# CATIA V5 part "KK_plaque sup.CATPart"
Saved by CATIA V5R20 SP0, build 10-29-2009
Part number: plaque fixe de table elevatrice
Bounding box of the stored display mesh (mm): x -103 to 1197, y -355 to 45, z -50 to 50
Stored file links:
  G:\Khaled_CFAO_2011\ST2M\ST2M_GR2\tcorbin\Khaled\CAD_ThinkMOTION\KK_plaque sup.CATPart
  F:\Thinkmotionperso\assemblage robot\ass_skl_robot.CATProduct
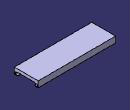
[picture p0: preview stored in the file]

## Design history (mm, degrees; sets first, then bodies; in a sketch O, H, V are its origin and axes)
External parameters (linked from other documents)
  `External.largeur table` = 400 mm
Set1
  Extract1: ExtractElem edge [face of Pad2 from Sketch2.L6 | face of Pad2 from Sketch2.L5]
  Extract2: ExtractElem edge [face of Pad2 from Sketch2.L13 | face of Pad2 from Sketch2.L12]
  Extract3: ExtractElem face of DatumSurface1
  DatumSurface1
  Extract4: ExtractElem face of DatumSurface2
  DatumSurface2
  Fill1: Boundary edge of DatumSurface1
  Healing1: BodyToHeal (Fill1; Extract3), TangencyAngle 0.5, SharpnessAngle 0.5
  Fill2: Boundary edge of DatumSurface2
  Healing2: BodyToHeal (Fill2; Extract4), TangencyAngle 0.5, SharpnessAngle 0.5
Body1 (main body)
  Sketch1 on xy-plane, origin (0, 0, 0), H (1, 0, 0), V (0, 1, 0)
    line L1 (-103, 45) -> (1197, 45)
    line L2 (1197, 45) -> (1197, -355)
    line L3 (1197, -355) -> (-103, -355)
    line L4 (-103, -355) -> (-103, 45)
    length L1 = 1300
    length L4 = 400 {= `External.largeur table`}
    horizontal: L1 H, L3 H
    vertical: L2 V, L4 V
  Pad1: profile Sketch1, direction (0, 0, 1), length 50
  Sketch2 on face of Pad1 from Sketch1.L2, origin (1197, 0, 0), H (0, 1, 0), V (0, 0, 1)
    point P1 (-15, 0)
    line L1 (-15, 0) -> (45, 0)
    line L2 (45, 0) -> (45, -50)
    line L3 (45, -50) -> (-15, -50)
    line L4 (-15, -50) -> (-15, -40)
    line L5 (-15, -40) -> (30, -40)
    line L6 (30, -40) -> (30, -10)
    line L7 (30, -10) -> (-15, -10)
    point P8 (-15, -10)
    line L8 (-15, -10) -> (-15, 0)
    point P9 (-355, 0)
    line L9 (-355, 0) -> (-295, 0)
    line L10 (-295, 0) -> (-295, -10)
    line L11 (-295, -10) -> (-340, -10)
    line L12 (-340, -10) -> (-340, -40)
    line L13 (-340, -40) -> (-295, -40)
    line L14 (-295, -40) -> (-295, -50)
    line L15 (-295, -50) -> (-355, -50)
    line L16 (-355, -50) -> (-355, 0)
    reference projected point E1 (-355, 0) from vertex [face of Pad1 from Sketch1.L2 | start face of Pad1 | face of Pad1 from Sketch1.L3]
    length L6 = 30
    length L2 = 50
    length L4 = 10
    length L16 = 50
    length L12 = 30
    length L14 = 10
    length L3 = 60
    length L15 = 60
    length L7 = 45
    length L11 = 45
    length L9 = 60
    coincidence: P1 H, P8 L4, P9 H, P9 E1
    horizontal: L1 H, L3 H, L5 H, L7 H, L9 H, L11 H, L13 H, L15 H
    vertical: L2 V, L4 V, L6 V, L8 V, L10 V, L12 V, L14 V
    perpendicularity: L16 L9
  Pad2: profile Sketch2, direction (-1, 0, 0), length 1300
